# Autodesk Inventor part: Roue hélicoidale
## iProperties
Shininess: 64.0
Length Units: 11269
Angle Units: 11279
Time Units: 11290
Mass Units: 11283
Length Display Precision: 3
Angle Display Precision: 2
Compacted: True
Part Number: Roue hélicoidale
Document SubType Name: Modeling
Created: 2003-05
Material: Delrin - Blanc
Designer: Philippe
Density: 0.0
Volumn: 0.0
Area: 0.0
PropertySet Name: Model Information
Control State: 0
Master: False
Checked Out: False
Author: Philippe
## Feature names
1. Révolution1 [Revolution]
2. Hélicoïde1
3. Hélicoïde2
4. Réseau circulaire1 [Circular Pattern]
5. Réseau circulaire2 [Circular Pattern]
